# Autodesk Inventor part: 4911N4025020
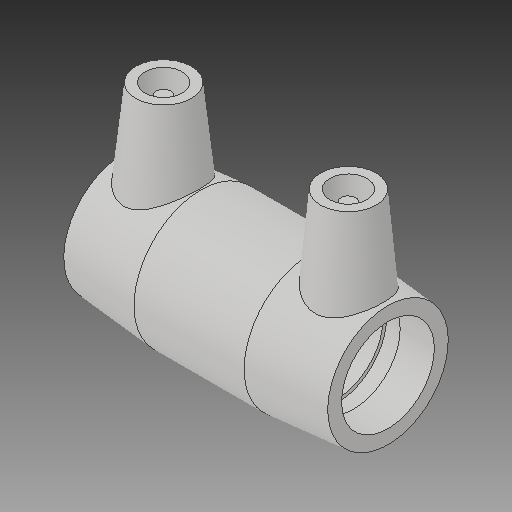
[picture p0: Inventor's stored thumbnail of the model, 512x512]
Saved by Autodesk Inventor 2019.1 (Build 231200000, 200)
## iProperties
Created: 2017-06
Part Number: 4911N4025020
Material: Generic
Description: PLASSON ASTM REDUCING COUPLING ADAPTOR 25-3/4''
Document SubType Name: Modeling
Designer: KIM
Mass: 54.8237 g
Surface Area: 155.252 cm^2
Volume: 54.8237 cm^3
Density: 1 g/cm^3
Appearance: Default
Author: KIM
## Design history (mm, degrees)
derived "4911N.ipt"
feature "Solid1::4911N.ipt"
tag "TaggingFeature1"
body "Solid1"
other parameters: "d0" = 71.12, "d2" = 36.068, "d3" = 34.544, "d4" = 20.7264, "d5" = 32.4612, "d7" = 26.6, "d8" = 168 deg, "d10" = 13.8176, "d11" = 4.60587, "d14" = 17.6296, "d22" = 108.92847, "d29" = 38.1, "d30" = 15, "d31" = 24.892, "d34" = 6 deg, "d41" = 4, "d42" = 14, "d43" = 0, "d48" = 36.068, "d49" = 25, "d50" = 36.068, "d52" = 23.94, "d53" = 13.8176, "d54" = 4.60587, "d55" = 168 deg, "d56" = 20.7264, "d57" = 34.544, "d58" = 32.4612, "d59" = 1.7272, "d60" = 135 deg, "d61" = 38.1, "d62" = 15, "d64" = 4, "d66" = 5 deg, "d67" = 14, "d68" = 0, "d69" = 24.892, "d95" = 3, "d96" = 0, "d97" = 3, "d98" = 0, "d_1" = 26.6, "L_" = 71.12, "L_2" = 34.544, "D_1" = 36.068, "A_1" = 38.1, "d_2" = 12, "L_1" = 34.544, "d_" = 25, "A_" = 38.1, "D_" = 36.068
